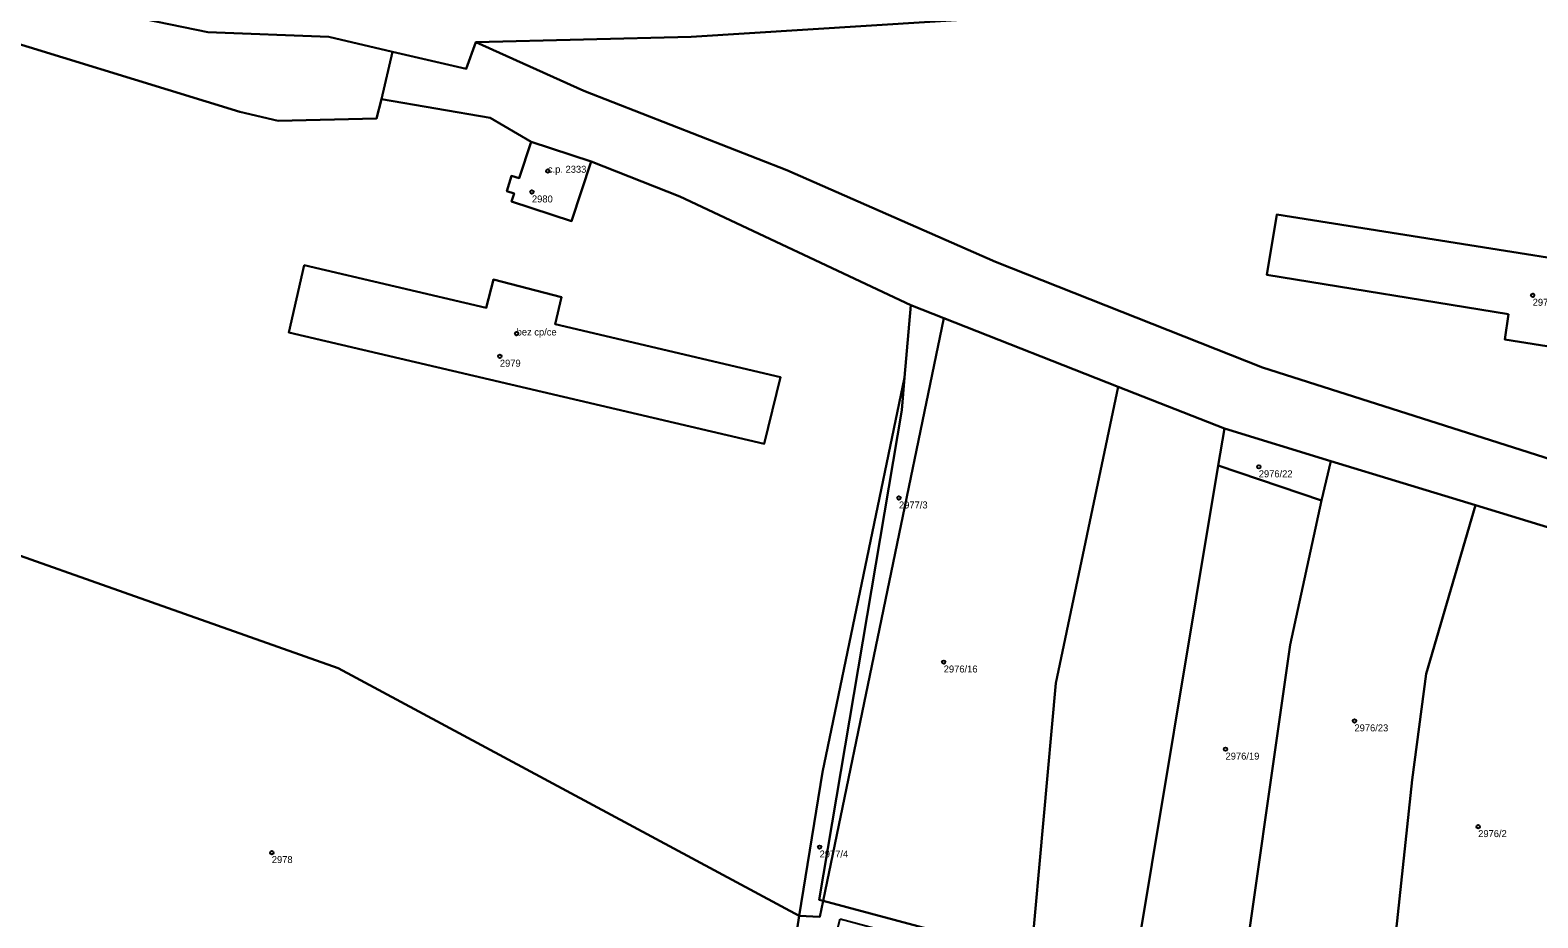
# Model space of a CAD drawing. Extents: x -878211 to -870363, y -1058464 to -1052522.
# Drawn here: x -873449 to -873233.3, y -1056021 to -1055893.9 of the extents above; entities that cross this region are included whole.
import ezdxf

# ---------------------------------------------------------------- set-up
doc = ezdxf.new("R2010")
doc.units = 0
for name, color, linetype in [('Definiční body', 7, 'Continuous'), ('Polygon budovy', 7, 'Continuous'), ('Polygon parcely', 7, 'Continuous')]:
    doc.layers.add(name, color=color, linetype=linetype)

msp = doc.modelspace()

# ---------------------------------------------------------------- linework, layer by layer
at = {"layer": 'Definiční body'}
for centre in [(-873374.91, -1055914.05994), (-873377.19, -1055917.06994), (-873234.02, -1055931.85994), (-873379.38, -1055937.34994), (-873381.78, -1055940.57994), (-873273.21, -1055956.40994), (-873324.68, -1055960.86994), (-873318.28, -1055984.34994), (-873259.52, -1055992.77994), (-873277.96, -1055996.81994), (-873241.82, -1056007.90994), (-873414.41, -1056011.62994), (-873336.04, -1056010.82994)]:
    msp.add_circle(centre, 0.25, dxfattribs=at)
at = {"layer": 'Polygon budovy'}
for points in [[(-873380.1, -1055914.76), (-873380.78, -1055916.94), (-873379.74, -1055917.3), (-873380.13, -1055918.42), (-873371.54, -1055921.22), (-873368.72, -1055912.71), (-873377.3, -1055909.88), (-873379.01, -1055915.1)], [(-873409.76, -1055927.55), (-873411.97, -1055937.15), (-873343.98, -1055953.12), (-873341.65, -1055943.57), (-873373.89, -1055936), (-873372.94, -1055932.13), (-873382.68, -1055929.61), (-873383.72, -1055933.64)]]:
    msp.add_lwpolyline(points, close=True, dxfattribs=at)
at = {"layer": 'Polygon parcely'}
for points in [[(-873549.49, -1055872.12), (-873562.38, -1055871.95), (-873562.4, -1055877.93), (-873558.54, -1055877.63), (-873533.21, -1055880.7), (-873481.19, -1055888.67), (-873459.41, -1055893.16), (-873418.96, -1055905.58), (-873413.5, -1055906.86), (-873399.42, -1055906.54), (-873398.71, -1055903.77), (-873397.12, -1055896.98), (-873406.23, -1055894.87), (-873423.56, -1055894.2), (-873485.18, -1055881.48), (-873523.82, -1055874.96)], [(-873368.72, -1055912.71), (-873377.3, -1055909.88), (-873379.01, -1055915.1), (-873380.1, -1055914.76), (-873380.78, -1055916.94), (-873379.74, -1055917.3), (-873380.13, -1055918.42), (-873371.54, -1055921.22)], [(-873237.49, -1055934.54), (-873272.05, -1055928.92), (-873270.64, -1055920.28), (-873196.19, -1055932.14), (-873197.65, -1055941.09), (-873229.33, -1055935.95), (-873229.88, -1055939.45), (-873237.99, -1055938.16)], [(-873237.49, -1055934.54), (-873237.99, -1055938.16), (-873229.88, -1055939.45), (-873229.33, -1055935.95), (-873197.65, -1055941.09), (-873196.19, -1055932.14), (-873270.64, -1055920.28), (-873272.05, -1055928.92)], [(-873409.76, -1055927.55), (-873383.72, -1055933.64), (-873382.68, -1055929.61), (-873372.94, -1055932.13), (-873373.89, -1055936), (-873341.65, -1055943.57), (-873343.98, -1055953.12), (-873411.97, -1055937.15)], [(-873409.76, -1055927.55), (-873411.97, -1055937.15), (-873343.98, -1055953.12), (-873341.65, -1055943.57), (-873373.89, -1055936), (-873372.94, -1055932.13), (-873382.68, -1055929.61), (-873383.72, -1055933.64)], [(-873336.09, -1056018.38), (-873335.54, -1056018.53), (-873318.27, -1055935.12), (-873322.98, -1055933.26), (-873323.88, -1055943.61), (-873324.28, -1055948.27)], [(-873318.27, -1055935.12), (-873335.54, -1056018.53), (-873305.75, -1056026.51), (-873302.26, -1055987.38), (-873293.33, -1055944.95)], [(-873333.09, -1056021.11), (-873291.67, -1056032.28), (-873279.01, -1055956.19), (-873278.12, -1055950.93), (-873293.33, -1055944.95), (-873302.26, -1055987.38), (-873305.75, -1056026.51), (-873335.54, -1056018.53), (-873336, -1056020.81), (-873338.98, -1056020.68), (-873346.78, -1056071.17), (-873331.06, -1056079.42), (-873315.95, -1056087.25), (-873311.01, -1056089.16), (-873306.55, -1056090.87), (-873301.67, -1056093.08), (-873293.3, -1056042.09), (-873335.55, -1056030.74)], [(-873338.98, -1056020.68), (-873336, -1056020.81), (-873335.54, -1056018.53), (-873336.09, -1056018.38), (-873324.28, -1055948.27), (-873323.88, -1055943.61), (-873335.63, -1056000.09)], [(-873264.24, -1055961.22), (-873262.89, -1055955.57), (-873278.12, -1055950.93), (-873279.01, -1055956.19)], [(-873291.67, -1056032.28), (-873276.51, -1056036.37), (-873268.73, -1055981.87), (-873264.24, -1055961.22), (-873279.01, -1055956.19)], [(-873242.2, -1055961.87), (-873262.89, -1055955.57), (-873264.24, -1055961.22), (-873268.73, -1055981.87), (-873276.51, -1056036.37), (-873255.6, -1056042.01), (-873251.26, -1056001.19), (-873249.24, -1055986.01)], [(-873422.69, -1056031.38), (-873418.27, -1056033.17), (-873411.98, -1056036.95), (-873406.26, -1056039.94), (-873391.99, -1056047.4), (-873370.31, -1056057.99), (-873349.99, -1056069.49), (-873346.78, -1056071.17), (-873338.98, -1056020.68), (-873404.93, -1055985.24), (-873484.29, -1055957.15), (-873490.94, -1056014.57), (-873481.86, -1056016.97), (-873478.93, -1056017.14), (-873462.56, -1056021.67), (-873456.37, -1056022.93), (-873434.77, -1056027.26), (-873432.72, -1056027.9)], [(-873218.66, -1055969.11), (-873242.2, -1055961.87), (-873249.24, -1055986.01), (-873251.26, -1056001.19), (-873255.6, -1056042.01), (-873232.73, -1056048.14), (-873224.62, -1055998.43)]]:
    msp.add_lwpolyline(points, close=True, dxfattribs=at)
for points in [[(-873485.18, -1055881.48), (-873423.56, -1055894.2), (-873406.23, -1055894.87), (-873397.12, -1055896.98), (-873386.62, -1055899.42), (-873385.21, -1055895.61), (-873354.4, -1055894.87), (-873303.59, -1055891.66)], [(-873194, -1055882.09), (-873245.3, -1055887.08), (-873272.16, -1055888.43), (-873303.59, -1055891.66), (-873354.4, -1055894.87), (-873385.21, -1055895.61), (-873369.76, -1055902.59), (-873340.72, -1055913.92), (-873310.89, -1055927.06), (-873272.67, -1055942.19), (-873208.47, -1055962.63)], [(-873484.29, -1055957.15), (-873404.93, -1055985.24), (-873338.98, -1056020.68), (-873335.63, -1056000.09), (-873323.88, -1055943.61), (-873322.98, -1055933.26), (-873356.04, -1055917.69), (-873368.72, -1055912.71), (-873371.54, -1055921.22), (-873380.13, -1055918.42), (-873379.74, -1055917.3), (-873380.78, -1055916.94), (-873380.1, -1055914.76), (-873379.01, -1055915.1), (-873377.3, -1055909.88), (-873383.19, -1055906.47), (-873398.71, -1055903.77), (-873399.42, -1055906.54), (-873413.5, -1055906.86), (-873418.96, -1055905.58), (-873459.41, -1055893.16)], [(-873208.47, -1055962.63), (-873272.67, -1055942.19), (-873310.89, -1055927.06), (-873340.72, -1055913.92), (-873369.76, -1055902.59), (-873385.21, -1055895.61), (-873386.62, -1055899.42), (-873397.12, -1055896.98), (-873398.71, -1055903.77), (-873383.19, -1055906.47), (-873377.3, -1055909.88), (-873368.72, -1055912.71), (-873356.04, -1055917.69), (-873322.98, -1055933.26), (-873318.27, -1055935.12), (-873293.33, -1055944.95), (-873278.12, -1055950.93), (-873262.89, -1055955.57), (-873242.2, -1055961.87), (-873218.66, -1055969.11)]]:
    msp.add_lwpolyline(points, dxfattribs=at)

# ---------------------------------------------------------------- texts
at = {"layer": 'Definiční body'}
for s, p in [('c.p. 2333', (-873374.91, -1055914.31)), ('2980', (-873377.19, -1055918.559)), ('2972', (-873234.02, -1055933.349)), ('bez cp/ce', (-873379.38, -1055937.6)), ('2979', (-873381.78, -1055942.069)), ('2976/22', (-873273.21, -1055957.899)), ('2977/3', (-873324.68, -1055962.359)), ('2976/16', (-873318.28, -1055985.839)), ('2976/23', (-873259.52, -1055994.269)), ('2976/19', (-873277.96, -1055998.309)), ('2976/2', (-873241.82, -1056009.399)), ('2978', (-873414.41, -1056013.119)), ('2977/4', (-873336.04, -1056012.319))]:
    msp.add_text(s, height=0.999996, dxfattribs=at).set_placement(p)

doc.saveas('drawing.dxf')
